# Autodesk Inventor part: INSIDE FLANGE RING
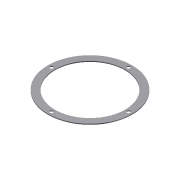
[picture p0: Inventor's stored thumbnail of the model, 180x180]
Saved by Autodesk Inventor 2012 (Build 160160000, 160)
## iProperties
Created: 2011-05
Part Number: INSIDE FLANGE RING
Material: Stainless Steel, 440C
Document SubType Name: Modeling
Designer: Dimitris
Mass: 2142.57 g
Surface Area: 1244.07 cm^2
Volume: 276.46 cm^3
Density: 7.75 g/cm^3
Author: Dimitris
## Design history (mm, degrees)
sketch "Sketch1"
  geometry: C1 r 240 at (0, 0); C2 r 200 at (0, 0); 1 further point
  constraints: 2 centre point, 1 coincident
  dimensions: "OD" = 480 diameter of C1; "ID" = 400 diameter of C2
extrude "Extrusion1" new body sketch "Sketch1" distance "d2" = 5; taper "d3" = 0 deg
sketch "Sketch2"
  geometry: C1 r 240 at (0, 0) reference; 3 further points
  constraints: 2 vertical alignment, 1 coincident, 2 other
  dimensions: "d15" = 20 dimension on C1
hole "Hole1" sketch "Sketch2" at (0, 220) diameter "d5" = 19; stored, may be unused: countersink angle "d9" = 90 deg, drill point angle "d11" = 118 deg; dims "d6" = 6, "d7" = 4, "d8" = 2, "d10" = 8
pattern_circular "Circular Pattern1" dims angle "d13" = 360 deg
body "Solid1"
